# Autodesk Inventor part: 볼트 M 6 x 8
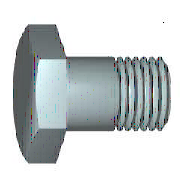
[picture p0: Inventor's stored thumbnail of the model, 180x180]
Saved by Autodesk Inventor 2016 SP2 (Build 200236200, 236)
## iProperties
Created: 2012-02
Part Number: 볼트 M 6 x 8
Material: 강철, 연강
Description: 6각 머리 볼트 및 6각 머리 나사
Document SubType Name: Modeling
Standard: KS B 1002
Designer: mduedu
Standards Organization: KS
Language: ko-KR
Size Designation: C  M 6 x 12
Categories: <MemberInstance><Categories><Category DisplayName="조임쇠" InternalName="e4da775c-781d-43d5-af7c-5136215cf5a6" Mnemonic="FSTN"><Category DisplayName="볼트" InternalN
Density: 1 g/cm^3
Appearance: 강철
IsCustomPart: 1
Author: mduedu
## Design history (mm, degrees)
sketch "스케치1"
  geometry: L1 (0, 3)-(8, 3); L2 (8, 3)-(8, 0); L3 (8, 0)-(0, 0); L4 (-2.4, 0)-(14.4, 0) reference; L5 (0, -0.6)-(0, 3.6) reference; L6 (0, 3)-(0, 0)
  constraints: 8 end point, 3 point on line, 1 collinear
  dimensions: "d2" = 6 diameter of L1 L3 (= GD); "d59" = 8 distance between parallel lines of L2 L5 (= NLG)
revolve "본체" sketch "스케치1" stored, may be unused: angle "d12" = 90 deg
sketch "스케치2"
  geometry: L1 (0, 5.774)-(5, 2.887); L2 (5, 2.887)-(5, -2.887); L3 (5, -2.887)-(0, -5.774); L4 (0, -5.774)-(-5, -2.887); L5 (-5, -2.887)-(-5, 2.887); L6 (-5, 2.887)-(0, 5.774); L7 (-7, 0)-(7, 0) reference; L8 (0, 8.083)-(0, -8.083) reference; 2 further points
  constraints: 12 end point, 2 midpoint, 1 coincident, 1 vertical, 11 other
  dimensions: "d11" = 10 distance between parallel lines of L5 L2 (= SW)
extrude "머리" join sketch "스케치2" distance "d3" = 4 (= KOH); taper "d4" = 0 deg
revolve "모따기1" stored, may be unused: angle "d21" = 90 deg
workplane "Work Plane1"
body "Solid1"
feature "스레드" dims "d15" = 9 (= GEL), "d16" = 0
chamfer "모따기2" distance "d6" = 0.61345 (= -0.5 x SPD + 0.5 x GD); stored, may be unused: second distance "d7" = 0.61355 (computed from GUL), angle "d55" = 45 deg
sketch "스케치4"
  geometry: L1 (-3.423, 6)-(-4, 5); L2 (-1.1, 0)-(-0.234, 0); L3 (-4.753, 0)-(0.519, 0) reference; L4 (-4, 6)-(-3.423, 6); L5 (-4, 5)-(-4, 6); L6 (0, 7.2)-(0, -1.2) reference
  constraints: 8 end point, 1 parallel, 1 perpendicular, 1 point on line
  dimensions: "d65" = 10 diameter of L1.end L2 (= SW); "d67" = 30 deg angle of L1 L5 (= ANG1); "d68" = 12 diameter of L4 L2 (= 1.2 x SW); "d69" = 4 distance between parallel lines of L5 L6 (= KOH)
other parameters: "NLG" = 8 [user parameter; used in 1 equation term], "GD" = 6 (= NND) [user parameter; used in 2 equation terms], "BDM" = 6 (= NND) [user parameter], "KOH" = 4 [user parameter; used in 2 equation terms], "GEL" = 9 [user parameter; used in 1 equation term], "SW" = 10 [user parameter; used in 5 equation terms], "SPD" = 4.7731 (= NND - 1.2269 x PTC) [user parameter; used in 1 equation term], "SD2" = 6 (= NND) [user parameter], "SD" = 0 [user parameter], "ANG1" = 30 deg [user parameter; used in 1 equation term], "GAL" = 0.61345 (= 0.61345 x PTC) [user parameter], "GUL" = 0.61345 (= 0.61345 x PTC) [user parameter; used in 1 equation term], "d8" = 0, "RR" = 0.25 [user parameter], "d58" = 0, "RR1" = 0.1 [user parameter], "GD1" = 4.7731 (= THREADDIA - 1.2269 x PTC) [user parameter], "THREADDIA" = 6 [user parameter; used in 1 equation term], "TOA" = 30 deg [user parameter], "PTC" = 1 [user parameter; used in 5 equation terms], "NND" = 6 [user parameter; used in 4 equation terms], "E0" = 11.55 (= 1.155 x SW) [user parameter]
